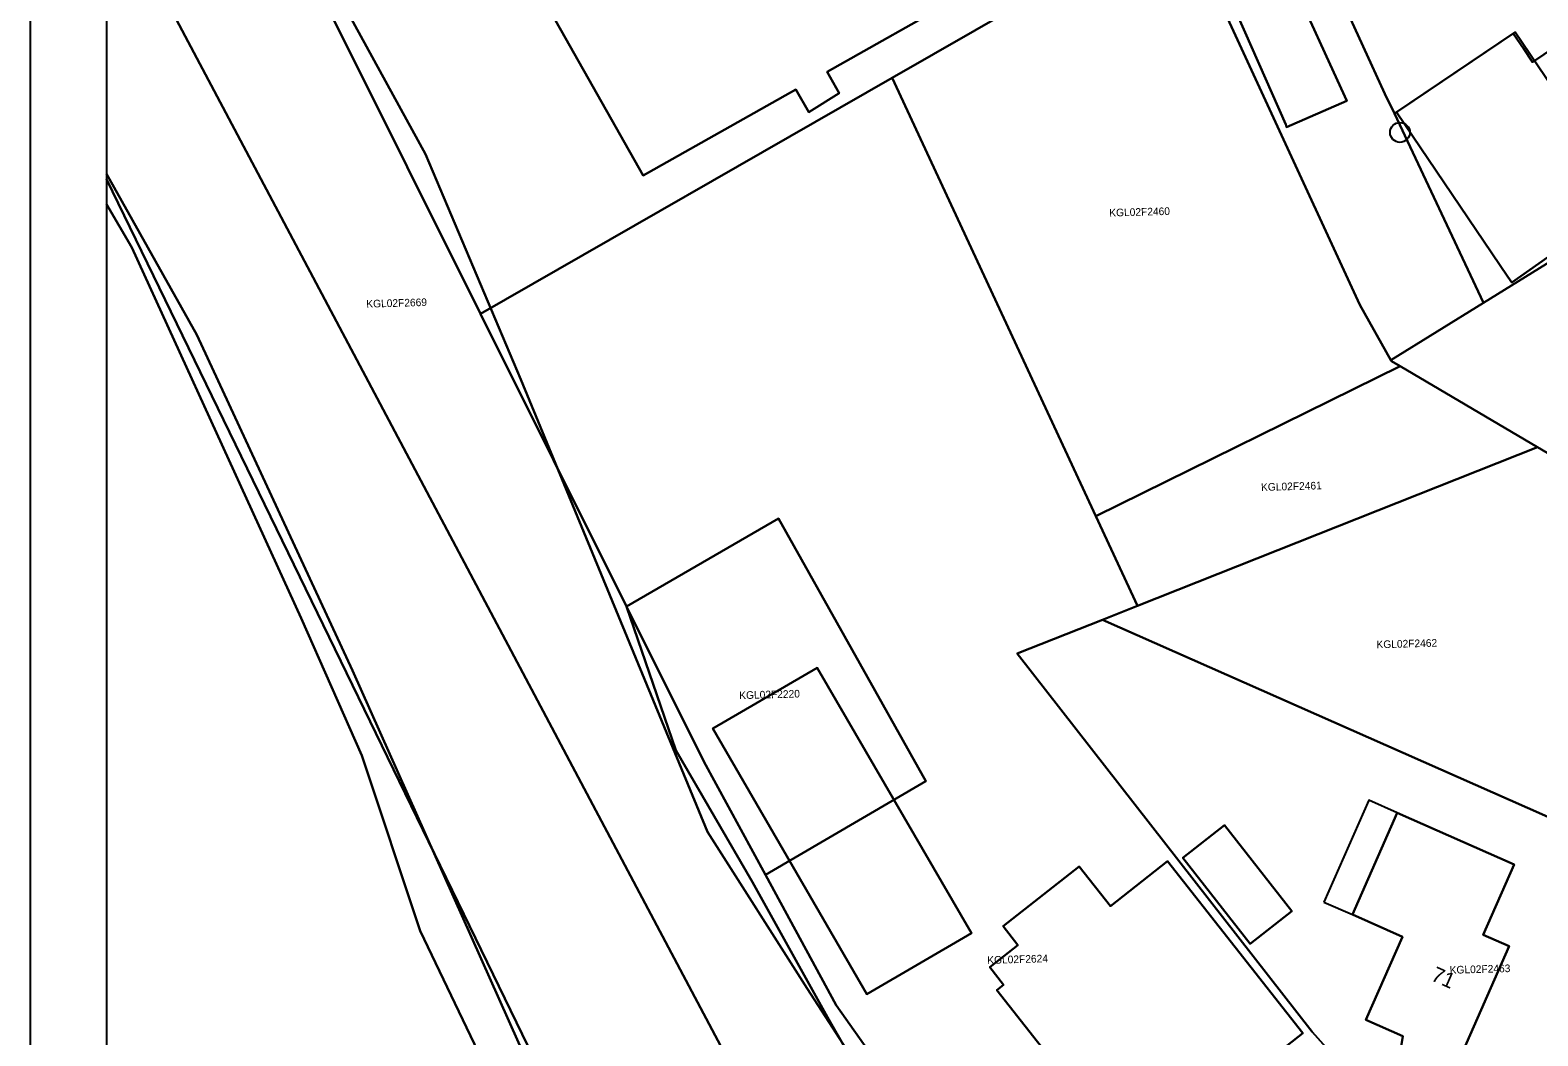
# Model space of a CAD drawing. Extents: x 124901 to 125496, y 515369 to 515789.
# Drawn here: x 124901.4 to 125000.2, y 515510.4 to 515576.3 of the extents above; entities that cross this region are included whole.
import ezdxf

# ---------------------------------------------------------------- set-up
doc = ezdxf.new("R2010")
doc.units = 0
for name, color, linetype in [('Alg Kaders', 7, 'Continuous'), ('Gebouw', 7, 'Continuous'), ('Luifel', 7, 'Continuous'), ('Onbegroeid terrein', 7, 'Continuous'), ('Perceelnummers', 7, 'Continuous'), ('Perceelsgrenzen', 7, 'Continuous'), ('Putten', 7, 'Continuous'), ('Teksten', 7, 'Continuous'), ('Vegetatie', 7, 'Continuous'), ('Water', 7, 'Continuous'), ('Wegen lokale weg', 7, 'Continuous')]:
    doc.layers.add(name, color=color, linetype=linetype)

msp = doc.modelspace()

# ---------------------------------------------------------------- linework, layer by layer
at = {"layer": 'Alg Kaders'}
for points in [[(125495.925, 515789.043), (124901.425, 515789.043), (124901.425, 515368.543), (125495.925, 515368.543)], [(125490.925, 515784.043), (124906.425, 515784.043), (124906.425, 515373.543), (125490.925, 515373.543)]]:
    msp.add_lwpolyline(points, close=True, dxfattribs=at)
at = {"layer": 'Gebouw'}
for points in [[(124953.656, 515573.582), (124971.175, 515583.466), (124963.357, 515597.324), (124933.784, 515580.64), (124941.602, 515566.782), (124951.601, 515572.423), (124952.463, 515570.923), (124954.442, 515572.183)], [(124998.525, 515559.764), (125006.205, 515565.157), (124998.754, 515576.171), (124991.164, 515571.056), (124990.966, 515570.923), (124998.271, 515560.139)], [(124953.014, 515534.496), (124946.16, 515530.514), (124956.269, 515513.114), (124963.123, 515517.096)], [(124988.965, 515511.421), (124991.376, 515510.357), (124991.132, 515508.727), (124994.201, 515508.267), (124994.332, 515509.138), (124995.075, 515508.81), (124998.358, 515516.25), (124996.657, 515517), (124998.694, 515521.615), (124991.025, 515524.999), (124988.078, 515518.32), (124991.368, 515516.868)], [(124979.689, 515524.18), (124976.963, 515522.041), (124981.378, 515516.414), (124984.104, 515518.553)], [(124964.313, 515514.871), (124965.224, 515513.715), (124964.774, 515513.36), (124973.825, 515501.866), (124984.84, 515510.54), (124975.958, 515521.82), (124972.22, 515518.877), (124970.167, 515521.485), (124965.187, 515517.564), (124966.161, 515516.326)]]:
    msp.add_lwpolyline(points, close=True, dxfattribs=at)
at = {"layer": 'Luifel'}
msp.add_lwpolyline([(124986.202, 515519.148), (124988.078, 515518.32), (124991.025, 515524.999), (124989.148, 515525.827)], close=True, dxfattribs=at)
at = {"layer": 'Onbegroeid terrein'}
for points in [[(124906.425, 515607.187), (124912.007, 515596.198), (124927.338, 515568.172), (124933.584, 515553.409), (124945.808, 515523.755), (124952.343, 515513.489), (124960.185, 515501.344)], [(124980.497, 515587.44), (124986.865, 515573.529), (124987.71, 515571.682), (124983.772, 515569.947), (124983.709, 515570.119), (124976.97, 515585.413)]]:
    msp.add_lwpolyline(points, dxfattribs=at)
for points in [[(124971.175, 515583.466), (124953.656, 515573.582), (124954.442, 515572.183), (124952.463, 515570.923), (124951.601, 515572.423), (124941.602, 515566.782), (124933.784, 515580.64), (124963.357, 515597.324)], [(125006.205, 515565.157), (124998.525, 515559.764), (124998.271, 515560.139), (124990.966, 515570.923), (124991.164, 515571.056), (124998.754, 515576.171)], [(124946.16, 515530.514), (124953.014, 515534.496), (124963.123, 515517.096), (124956.269, 515513.114)], [(124991.376, 515510.357), (124988.965, 515511.421), (124991.368, 515516.868), (124988.078, 515518.32), (124991.025, 515524.999), (124998.694, 515521.615), (124996.657, 515517), (124998.358, 515516.25), (124995.075, 515508.81), (124994.332, 515509.138), (124994.201, 515508.267), (124991.132, 515508.727)], [(124976.963, 515522.041), (124979.689, 515524.18), (124984.104, 515518.553), (124981.378, 515516.414)], [(124965.224, 515513.715), (124964.313, 515514.871), (124966.161, 515516.326), (124965.187, 515517.564), (124970.167, 515521.485), (124972.22, 515518.877), (124975.958, 515521.82), (124984.84, 515510.54), (124973.825, 515501.866), (124964.774, 515513.36)]]:
    msp.add_lwpolyline(points, close=True, dxfattribs=at)
at = {"layer": 'Perceelsgrenzen'}
for points in [[(124967.939, 515603.092), (124965.798, 515607.743), (124957.013, 515626.826), (124956.981, 515626.896), (124939.837, 515664.138), (124939.317, 515665.488), (124938.451, 515669.215), (124938.462, 515670.08), (124944.847, 515671.033), (124954.658, 515649.647), (124965.42, 515626.188), (124974.304, 515606.823), (124974.642, 515606.086), (124983.184, 515587.466), (124984.517, 515584.561), (124990.215, 515572.14), (124990.831, 515570.832), (124996.668, 515558.434), (124990.606, 515554.681), (124988.558, 515558.301), (124976.736, 515583.981)], [(125014.335, 515605.811), (125023.679, 515590.367), (125010.774, 515581.584), (124999.882, 515574.212), (124999.285, 515575.095), (124998.619, 515576.08), (124990.831, 515570.832), (124990.215, 515572.14), (124984.517, 515584.561), (124991.834, 515588.499), (124994.531, 515583.73), (125004.862, 515589.576), (125000.338, 515597.568)], [(124949.82, 515592.945), (124954.921, 515595.802), (124967.939, 515603.092), (124976.736, 515583.981), (124957.916, 515573.184), (124930.943, 515557.71), (124921.333, 515576.993), (124934.237, 515584.219), (124939.621, 515587.234), (124944.716, 515590.087)], [(125023.679, 515590.367), (125023.849, 515590.085), (125024.631, 515589.269), (125030.952, 515585.122), (125021.181, 515574.949), (125018.012, 515571.65), (125007.677, 515565.251), (124996.668, 515558.434), (124990.831, 515570.832), (124998.619, 515576.08), (124999.285, 515575.095), (124999.882, 515574.212), (125010.774, 515581.584)], [(124957.916, 515573.184), (124976.736, 515583.981), (124988.558, 515558.301), (124990.606, 515554.681), (124990.653, 515554.598), (124991.211, 515554.27), (124971.258, 515544.441)], [(124991.211, 515554.27), (124990.653, 515554.598), (124990.606, 515554.681), (124996.668, 515558.434), (125007.677, 515565.251), (125035.799, 515548.142), (125028.241, 515533.814), (125016.742, 515539.371), (125011.253, 515542.479), (125000.206, 515548.978)], [(124971.258, 515544.441), (124991.211, 515554.27), (125000.206, 515548.978), (124973.989, 515538.558)], [(124971.705, 515537.65), (124973.989, 515538.558), (125000.206, 515548.978), (125011.253, 515542.479), (125004.287, 515523.22)], [(124940.501, 515538.532), (124950.474, 515544.288), (124960.122, 515527.063), (124949.61, 515520.928), (124945.568, 515528.364)], [(124940.501, 515538.532), (124945.568, 515528.364), (124949.61, 515520.928), (124954.254, 515512.387), (124961.521, 515502.086), (124970.53, 515491.146), (124971.406, 515490.274), (124968.664, 515487.719), (124965.419, 515495.246), (124962.674, 515498.659), (124958.344, 515504.072), (124954.973, 515509.339), (124953.675, 515511.607), (124948.774, 515520.44), (124943.739, 515529.107)], [(125002.193, 515491.874), (124985.446, 515510.648), (124966.122, 515535.431), (124971.705, 515537.65), (125004.287, 515523.22), (125002.945, 515519.509), (125007.382, 515516.876), (125012.299, 515514.356), (125002.221, 515491.957)]]:
    msp.add_lwpolyline(points, close=True, dxfattribs=at)
for points in [[(124906.425, 515606.905), (124921.333, 515576.993), (124930.943, 515557.71), (124940.501, 515538.532), (124943.739, 515529.107), (124948.774, 515520.44), (124953.675, 515511.607), (124954.973, 515509.339), (124958.344, 515504.072), (124962.674, 515498.659), (124965.419, 515495.246), (124968.664, 515487.719), (124969.251, 515486.357), (124970.049, 515483.901), (124971.604, 515479.591), (124972.78, 515477.748), (124970.518, 515472.925), (124969.575, 515470.638), (124967.68, 515475.755), (124963.455, 515482.582), (124954.711, 515494.572), (124906.425, 515585.657)], [(124906.425, 515585.657), (124954.711, 515494.572)], [(124961.521, 515502.086), (124954.254, 515512.387), (124949.61, 515520.928), (124960.122, 515527.063), (124950.474, 515544.288), (124940.501, 515538.532), (124930.943, 515557.71), (124957.916, 515573.184), (124971.258, 515544.441), (124973.989, 515538.558), (124971.705, 515537.65), (124966.122, 515535.431), (124985.446, 515510.648), (125002.193, 515491.874)], [(124906.425, 515396.387), (124928.221, 515415.413), (124937.622, 515423.904), (124948.404, 515434.407), (124953.911, 515444.595), (124956.015, 515453.428), (124955.804, 515462.554), (124949.282, 515479.896), (124944.986, 515487.708), (124939.446, 515498.619), (124906.425, 515566.534)], [(124906.425, 515566.534), (124939.446, 515498.619), (124944.986, 515487.708), (124949.282, 515479.896), (124955.804, 515462.554), (124956.015, 515453.428), (124953.911, 515444.595), (124948.404, 515434.407), (124937.622, 515423.904), (124928.221, 515415.413), (124906.425, 515396.387)]]:
    msp.add_lwpolyline(points, dxfattribs=at)
at = {"layer": 'Putten'}
msp.add_circle((124991.2, 515569.6), 0.65, dxfattribs=at)
at = {"layer": 'Vegetatie'}
msp.add_lwpolyline([(124932.815, 515505.082), (124926.994, 515517.253), (124923.158, 515528.762), (124919.189, 515537.758), (124908.081, 515562.051), (124906.425, 515564.889)], dxfattribs=at)
at = {"layer": 'Water'}
for points in [[(124960.185, 515501.344), (124952.343, 515513.489), (124945.808, 515523.755), (124933.584, 515553.409), (124927.338, 515568.172), (124912.007, 515596.198), (124906.425, 515607.187)], [(124906.425, 515566.886), (124912.354, 515556.328), (124922.546, 515534.323), (124933.984, 515508.717)], [(124933.984, 515508.717), (124922.546, 515534.323), (124912.354, 515556.328), (124906.425, 515566.886)], [(124906.425, 515564.889), (124908.081, 515562.051), (124919.189, 515537.758), (124923.158, 515528.762), (124926.994, 515517.253), (124932.815, 515505.082)]]:
    msp.add_lwpolyline(points, dxfattribs=at)
at = {"layer": 'Wegen lokale weg'}
msp.add_lwpolyline([(124976.97, 515585.413), (124983.709, 515570.119), (124983.772, 515569.947), (124987.71, 515571.682), (124986.865, 515573.529), (124980.497, 515587.44)], dxfattribs=at)

# ---------------------------------------------------------------- texts
at = {"layer": 'Perceelnummers'}
for s, rotation, p in [('KGL02F2460', 1.62953, (124972.155, 515564.083)), ('KGL02F2669', 1.62896, (124923.462, 515558.113)), ('KGL02F2461', 1.62964, (124982.101, 515546.095)), ('KGL02F2462', 1.62973, (124989.668, 515535.78)), ('KGL02F2220', 1.62924, (124947.903, 515532.447)), ('KGL02F2624', 1.62943, (124964.159, 515515.089)), ('KGL02F2463', 1.62979, (124994.464, 515514.443))]:
    msp.add_text(s, height=0.5, rotation=rotation, dxfattribs=at).set_placement(p)
at = {"layer": 'Teksten'}
msp.add_text('71', height=1, rotation=336.2, dxfattribs=at).set_placement((124993.168, 515514.037))

doc.saveas('drawing.dxf')
